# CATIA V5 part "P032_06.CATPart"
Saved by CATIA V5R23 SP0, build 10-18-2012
Part number: 05-LICP-T02-E-S03-P032_06
Bounding box of the stored display mesh (mm): x 19.53 to 20.265, y -11.193 to 11.193, z -11.202 to 11.202
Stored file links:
  C:\wamp\www\COURS\CONCEPTION GMP1\TITRE 02-SEMESTRE 2\03-TP7-PRESSE MECANIQUE\eleve\P032_06.CATPart
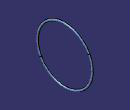
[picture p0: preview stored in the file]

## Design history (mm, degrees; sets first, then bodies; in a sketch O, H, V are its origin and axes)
Body1 (main body)
  Solid1: solid without history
